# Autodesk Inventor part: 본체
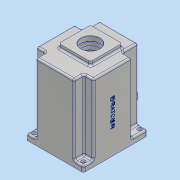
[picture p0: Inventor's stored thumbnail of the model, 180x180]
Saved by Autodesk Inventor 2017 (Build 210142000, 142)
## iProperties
Part Number: 본체
Material: 알루미늄 6061
Document SubType Name: Modeling
Designer: MRC
Density: 2.7 g/cm^3
Appearance: 알루미늄 - 평지
Mass: 1404.25 g
Surface Area: 1170.72 cm^2
Volume: 520.092 cm^3
Author: MRC
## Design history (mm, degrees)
sketch "스케치1"
  geometry: L1 (-49, 60)-(49, 60); L2 (49, 60)-(49, -50); L3 (49, -50)-(-49, -50); L4 (-49, -50)-(-49, 60); L5 (-49, 60)-(49, -50); L6 (49, 60)-(-49, -50); 3 further points
  constraints: 12 end point, 3 midpoint, 2 parallel, 1 horizontal, 1 perpendicular, 1 vertical alignment
  dimensions: "d1" = 50 distance from line of L3 point (0, 0); "d2" = 110 distance of L3.end L1.start; "d3" = 98 distance of L2.end L3.end
extrude "돌출1" new body sketch "스케치1" distance "d4" = 10; taper "d5" = 0 deg
sketch "스케치2"
  geometry: L1 (49, 60)-(-49, 60) reference; L2 (-49, -50)-(49, -50) reference; L3 (49, -50)-(49, 60) reference; L4 (-33, -50)-(33, -50); L5 (33, -50)-(33, 60); L6 (33, 60)-(-33, 60); L7 (-33, 60)-(-33, -50); L8 (-33, -50)-(33, 60); L9 (33, -50)-(-33, 60); L10 (-49, -33)-(49, -33); L11 (49, -33)-(49, 33); L12 (49, 33)-(-49, 33); L13 (-49, 33)-(-49, -33); L14 (-49, -33)-(49, 33); L15 (49, -33)-(-49, 33); 6 further points
  constraints: 24 end point, 7 midpoint, 4 parallel, 2 collinear, 2 horizontal, 2 perpendicular, 2 vertical alignment, 1 point on line
  dimensions: "d6" = 66 distance between parallel lines of L5 L7; "d7" = 27 distance between parallel lines of L1 L12; "d8" = 17 distance between parallel lines of L2 L10
extrude "돌출2" join sketch "스케치2" distance "d9" = 120; taper "d10" = 0 deg
sketch "스케치3"
  geometry: L1 (-27, -16)-(27, -16); L2 (27, -16)-(27, 38); L3 (27, 38)-(-27, 38); L4 (-27, 38)-(-27, -16); L5 (-27, -16)-(27, 38); L6 (27, -16)-(-27, 38); 3 further points
  constraints: 12 end point, 3 midpoint, 2 parallel, 1 horizontal, 1 perpendicular, 1 vertical alignment
  dimensions: "d11" = 11 distance of point (0, 0) point (0, 11); "d12" = 54 distance of L2.end L3.end; "d13" = 54 distance of L1.end L2.end
extrude "돌출3" join sketch "스케치3" distance "d14" = 7; taper "d15" = 0 deg
sketch "스케치4"
  geometry: L1 (0, 0)-(98, 0) reference; C1 r 22.5 at (49, -40); 2 further points
  constraints: 1 centre point, 1 midpoint, 1 vertical alignment
  dimensions: "d16" = 40 distance from line of L1 C1.centre; "d19" = 45 diameter of C1
extrude "돌출4" join sketch "스케치4" distance "d20" = 10; taper "d21" = 0 deg
sketch "스케치5"
  geometry: L1 (0, 0)-(98, 0) reference; C1 r 15 at (49, -89); 2 further points
  constraints: 1 centre point, 1 midpoint, 1 vertical alignment
  dimensions: "d22" = 89 distance from line of C1.centre L1; "d23" = 30 diameter of C1
extrude "돌출5" join sketch "스케치5" distance "d24" = 5; taper "d25" = 0 deg
sketch "스케치6"
  geometry: L1 (-23, 35.143)-(-23, 50); L2 (-23, 50)-(23, 50); L3 (23, 50)-(23, 35.143); A1 r 42 centre (0, 0) between (23, 35.143) and (-23, 35.143); 2 further points
  constraints: 6 end point, 2 perpendicular, 2 point on circle, 1 centre point, 1 coincident, 1 midpoint, 1 vertical, 1 vertical alignment
  dimensions: "d26" = 84 diameter of A1; "d27" = 46 distance between parallel lines of L3 L1; "d28" = 50 distance from line of point (0, 0) L2
extrude "돌출6" cut sketch "스케치6" distance "d29" = 121; taper "d30" = 0 deg
sketch "스케치7"
  geometry: L1 (-23, 35.143)-(-23, 50) reference; L2 (-23, 50)-(23, 50) reference; L3 (23, 50)-(23, 35.143) reference; L4 (-26, 36.729)-(-26, 53); L5 (-26, 53)-(26, 53); L6 (26, 53)-(26, 36.729); A1 r 42 centre (0, 0) between (-23, 35.143) and (23, 35.143) reference; A2 r 45 centre (0, 0) between (-26, 36.729) and (26, 36.729)
  constraints: 6 end point, 2 point on circle, 1 centre point, 3 other
  dimensions: "d31" = 3 distance between parallel lines of L5 L2
extrude "돌출7" cut sketch "스케치7" distance "d32" = 9; taper "d33" = 0 deg
sketch "스케치8"
  geometry: C1 r 21 at (0, 11); C2 r 15 at (0, -20); A1 r 42 centre (0, 0) between (-23, 35.143) and (23, 35.143) reference
  constraints: 2 centre point, 2 vertical alignment
  dimensions: "d34" = 42 diameter of C1; "d35" = 30 diameter of C2; "d36" = 11 distance of A1.centre C1.centre; "d37" = 20 distance of A1.centre C2.centre
extrude "돌출8" join sketch "스케치8" distance "d38" = 7; taper "d39" = 0 deg
hole "구멍1" diameter "d42" = 19; stored, may be unused: countersink angle "d46" = 90 deg, drill point angle "d48" = 0 deg; dims "d40" = 10, "d41" = 10, "d43" = 6, "d44" = 22, "d45" = 7, "d47" = 10
hole "구멍2" diameter "d51" = 28; stored, may be unused: countersink angle "d55" = 90 deg, drill point angle "d57" = 0 deg; dims "d49" = 10, "d50" = 10, "d52" = 6, "d53" = 35, "d54" = 10, "d56" = 50
sketch "스케치9"
  geometry: C1 r 14 at (0, 11) reference; C2 r 16 at (0, 11); 1 further point
  constraints: 1 centre point, 1 coincident
  dimensions: "d58" = 32 diameter of C2
extrude "돌출9" cut sketch "스케치9" distance "d59" = 8.3; taper "d60" = 0 deg
sketch "스케치10"
  geometry: C1 r 15 at (0, 0) reference; C2 r 10 at (0, 0); 1 further point
  constraints: 1 centre point, 1 coincident
  dimensions: "d61" = 20 diameter of C2
extrude "돌출10" cut sketch "스케치10" distance "d62" = 38.8; taper "d63" = 0 deg
sketch "스케치11"
  geometry: C1 r 10 at (23, -32) reference; C2 r 15 at (23, -32); 1 further point
  constraints: 1 centre point, 1 coincident
  dimensions: "d64" = 30 diameter of C2
extrude "돌출11" cut sketch "스케치11" distance "d65" = 5; taper "d66" = 0 deg
hole "구멍3" diameter "d69" = 33.376; stored, may be unused: countersink angle "d73" = 90 deg, drill point angle "d75" = 0 deg; dims "d67" = 10, "d68" = 10, "d70" = 30, "d71" = 35, "d72" = 10, "d74" = 30
sketch "스케치12"
  geometry: L1 (-36, 4)-(-41.809, 4); L2 (-36, -4)-(-41.809, -4); A1 r 42 centre (0, 0) between (-23, 35.143) and (23, 35.143) reference; A2 r 4 centre (-36, 0) between (-36, 4) and (-36, -4)
  constraints: 4 end point, 4 point on circle, 2 tangent, 1 centre point, 1 horizontal, 1 horizontal alignment, 1 parallel
  dimensions: "d76" = 36 distance of A1.centre A2.centre; "d77" = 8 diameter of A2
extrude "돌출12" join sketch "스케치12" stored distance "d78" = 5; taper "d79" = 0 deg
hole "구멍4" diameter "d82" = 3.242; stored, may be unused: countersink angle "d86" = 90 deg, drill point angle "d88" = 118 deg; dims "d83" = 7, "d84" = 35, "d85" = 10, "d87" = 9, "d89" = 10, "d90" = 10
fillet "모깎기1" dims "d91" = 6, "d92" = 3
fillet "모깎기2" dims "d93" = 3
fillet "모깎기3" dims "d94" = 3
fillet "모깎기4" dims "d95" = 3
fillet "모깎기5" dims "d96" = 3
sketch "스케치13"
  geometry: L1 (-49, 57)-(-49, -47) reference; L2 (-46, -50)-(46, -50) reference; C1 r 3.5 at (-42, -43)
  constraints: 1 centre point
  dimensions: "d97" = 7 diameter of C1; "d98" = 7 distance from line of L1 C1.centre; "d99" = 7 distance from line of L2 C1.centre
extrude "돌출13" cut sketch "스케치13" distance "d100" = 10; taper "d101" = 0 deg
chamfer "모따기1" distance "d108" = 1; stored, may be unused: second distance "d109" = 2, angle "d110" = 45 deg
chamfer "모따기2" distance "d111" = 0.8; stored, may be unused: second distance "d112" = 2, angle "d113" = 30 deg
fillet "모깎기6" dims "d114" = 0.3
fillet "모깎기7" dims "d115" = 3
sketch "스케치14"
  geometry: L1 (-130, 104)-(-130, 83) reference; 2 further points
  constraints: 1 horizontal alignment, 1 other
  dimensions: "d116" = 65 distance from line of point (-65, 47) L1
feature "엠보싱1" sketch "스케치14" dims "d117" = 0.5, "d118" = 0
chamfer "모따기3" distance "d119" = 1; stored, may be unused: second distance "d120" = 2, angle "d121" = 45 deg
node "솔리드1"
mirror "미러1"
pattern_linear "직사각형 패턴1" dims "d104" = 84, "d107" = 96
